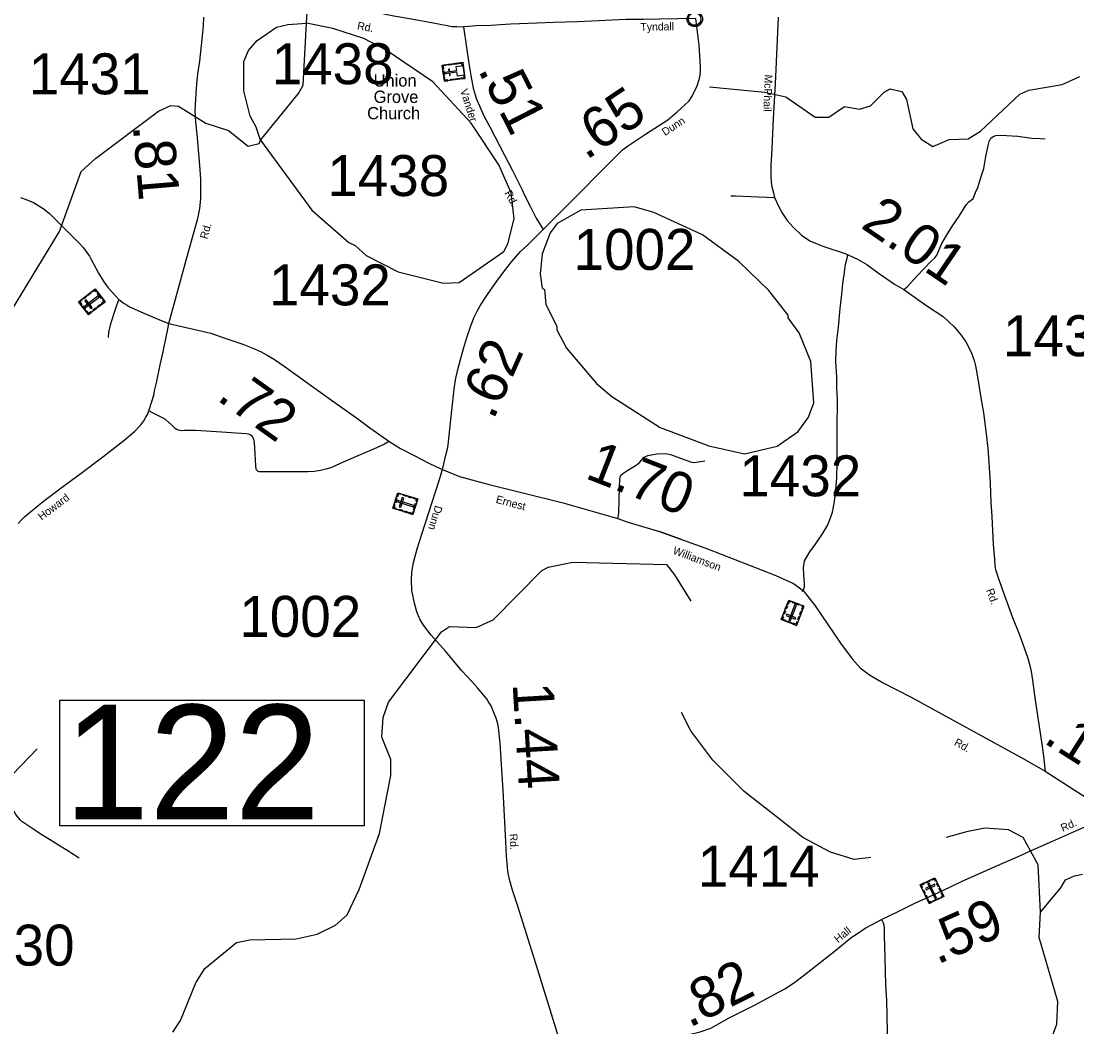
# Model space of a CAD drawing. Extents: x 2093524 to 2270757, y 289120 to 570408.
# Drawn here: x 2126907 to 2139794, y 473012 to 485292 of the extents above; entities that cross this region are included whole.
import ezdxf

# ---------------------------------------------------------------- set-up
doc = ezdxf.new("R2010")
doc.units = 0
for name, color, linetype in [('Exist Civil Demographics Community CELL', 7, 'Continuous'), ('Exist Cultural Cemetery CELL', 7, 'Continuous'), ('Exist Cultural Church with Cemetery CELL', 7, 'Continuous'), ('Exist Cultural Church with Cemetery Label', 7, 'Continuous'), ('Exist Hydrographic Creek Single Shore', 7, 'Continuous'), ('Exist Hydrographic Misc Water Feature', 7, 'Continuous'), ('Exist Hydrographic Pond Under 1500 Sq Ft', 7, 'Continuous'), ('Exist Road Non-System Type 51', 7, 'Continuous'), ('Exist Road Secondary Mileage Hundredths English Label', 7, 'Continuous'), ('Exist Road Secondary Structure Standard Bridge Number Label', 7, 'Continuous'), ('Exist Road Secondary Type 51 Attributed', 7, 'Continuous'), ('Exist Road Secondary Type 51 Label', 7, 'Continuous'), ('Exist Road Secondary Type 51 Number Label', 7, 'Continuous')]:
    doc.layers.add(name, color=color, linetype=linetype)

msp = doc.modelspace()

# ---------------------------------------------------------------- linework, layer by layer
at = {"layer": 'Exist Civil Demographics Community CELL'}
msp.add_lwpolyline([(2135205, 485294), (2135203, 485288), (2135200, 485283), (2135197, 485277), (2135194, 485272), (2135191, 485267), (2135186, 485262), (2135181, 485257), (2135176, 485253), (2135171, 485250), (2135167, 485247), (2135160, 485244), (2135153, 485241), (2135147, 485240), (2135140, 485239), (2135136, 485238), (2135131, 485238), (2135126, 485238), (2135121, 485238), (2135116, 485239), (2135110, 485240), (2135105, 485242), (2135100, 485243), (2135095, 485245), (2135092, 485248), (2135085, 485252), (2135079, 485256), (2135074, 485260), (2135070, 485265), (2135067, 485269), (2135064, 485273), (2135060, 485281), (2135058, 485284), (2135056, 485288), (2135054, 485296)], dxfattribs=at)
for centre, radius in [((2135130, 485317), 94.3), ((2135129, 485317), 76.7)]:
    msp.add_circle(centre, radius, dxfattribs=at)
at = {"layer": 'Exist Cultural Cemetery CELL'}
for points in [[(2127730, 481709), (2127608, 481866), (2127810, 482022), (2127932, 481864)], [(2127760, 481969), (2127725, 481942), (2127718, 481951), (2127753, 481978)], [(2127830, 481995), (2127821, 481988), (2127808, 482006), (2127776, 481981), (2127769, 481990), (2127810, 482022)], [(2127887, 481903), (2127836, 481970), (2127845, 481977), (2127896, 481909)], [(2127643, 481893), (2127650, 481884), (2127624, 481864), (2127649, 481832), (2127640, 481825), (2127608, 481866)], [(2127708, 481928), (2127673, 481902), (2127666, 481911), (2127701, 481937)], [(2127687, 481813), (2127698, 481798), (2127859, 481922), (2127847, 481937)], [(2127759, 481782), (2127774, 481794), (2127702, 481887), (2127687, 481876)], [(2127876, 481821), (2127842, 481795), (2127835, 481804), (2127869, 481830)], [(2127911, 481890), (2127902, 481883), (2127916, 481866), (2127884, 481841), (2127890, 481832), (2127932, 481864)], [(2127685, 481767), (2127653, 481808), (2127662, 481815), (2127694, 481774)], [(2127764, 481735), (2127757, 481744), (2127732, 481724), (2127707, 481756), (2127698, 481750), (2127730, 481709)], [(2127823, 481780), (2127789, 481754), (2127782, 481763), (2127816, 481789)], [(2131446, 479345), (2131506, 479534), (2131749, 479457), (2131688, 479267)], [(2131548, 479521), (2131544, 479510), (2131514, 479520), (2131501, 479482), (2131491, 479485), (2131506, 479534)], [(2131614, 479488), (2131573, 479501), (2131576, 479512), (2131617, 479499)], [(2131487, 479332), (2131490, 479342), (2131460, 479352), (2131472, 479391), (2131461, 479394), (2131446, 479345)], [(2131468, 479415), (2131484, 479465), (2131495, 479461), (2131479, 479412)], [(2131507, 479440), (2131501, 479422), (2131694, 479360), (2131700, 479378)], [(2131523, 479363), (2131541, 479357), (2131577, 479469), (2131559, 479475)], [(2131677, 479468), (2131635, 479481), (2131639, 479492), (2131680, 479479)], [(2131695, 479325), (2131721, 479406), (2131731, 479403), (2131706, 479322)], [(2131739, 479425), (2131728, 479429), (2131734, 479450), (2131696, 479462), (2131699, 479473), (2131749, 479457)], [(2131557, 479309), (2131516, 479322), (2131520, 479333), (2131561, 479320)], [(2131621, 479288), (2131580, 479302), (2131584, 479312), (2131625, 479299)], [(2131698, 479299), (2131687, 479302), (2131680, 479281), (2131642, 479293), (2131639, 479283), (2131688, 479267)], [(2136371, 477912), (2136185, 477984), (2136276, 478221), (2136462, 478150)], [(2136307, 478210), (2136303, 478199), (2136282, 478207), (2136268, 478169), (2136257, 478173), (2136276, 478221)], [(2136237, 478088), (2136222, 478048), (2136211, 478052), (2136227, 478092)], [(2136261, 478150), (2136245, 478110), (2136235, 478114), (2136250, 478154)], [(2136279, 477979), (2136297, 477972), (2136370, 478161), (2136352, 478168)], [(2136404, 478160), (2136325, 478190), (2136329, 478201), (2136408, 478171)], [(2136437, 478085), (2136421, 478044), (2136411, 478048), (2136426, 478089)], [(2136431, 478162), (2136427, 478151), (2136447, 478143), (2136433, 478106), (2136443, 478102), (2136462, 478150)], [(2136200, 478024), (2136211, 478020), (2136199, 477990), (2136237, 477976), (2136233, 477965), (2136185, 477984)], [(2136357, 477991), (2136364, 478008), (2136254, 478050), (2136247, 478033)], [(2136302, 477939), (2136253, 477958), (2136257, 477968), (2136306, 477950)], [(2136386, 477953), (2136376, 477957), (2136364, 477927), (2136326, 477941), (2136322, 477931), (2136371, 477912)], [(2136413, 478022), (2136397, 477982), (2136387, 477986), (2136402, 478026)], [(2137881, 474746), (2138061, 474832), (2138171, 474603), (2137991, 474517)], [(2137900, 474707), (2137910, 474712), (2137896, 474741), (2137933, 474759), (2137928, 474769), (2137881, 474746)], [(2137947, 474703), (2137955, 474686), (2138062, 474737), (2138054, 474753)], [(2137948, 474778), (2137995, 474801), (2138000, 474790), (2137953, 474768)], [(2137992, 474767), (2137975, 474759), (2138063, 474576), (2138080, 474584)], [(2138079, 474793), (2138069, 474788), (2138055, 474817), (2138019, 474800), (2138014, 474810), (2138061, 474832)], [(2138101, 474722), (2138082, 474762), (2138092, 474766), (2138111, 474727)], [(2137932, 474640), (2137913, 474679), (2137923, 474684), (2137942, 474645)], [(2137961, 474580), (2137942, 474619), (2137953, 474624), (2137971, 474585)], [(2138129, 474663), (2138111, 474702), (2138121, 474707), (2138140, 474668)], [(2138141, 474588), (2138136, 474599), (2138156, 474608), (2138138, 474645), (2138148, 474650), (2138171, 474603)], [(2138021, 474531), (2138016, 474541), (2137996, 474532), (2137979, 474568), (2137969, 474563), (2137991, 474517)], [(2138038, 474552), (2138115, 474589), (2138120, 474578), (2138043, 474542)]]:
    msp.add_lwpolyline(points, close=True, dxfattribs=at)
at = {"layer": 'Exist Cultural Church with Cemetery CELL'}
for points in [[(2132073, 484558), (2132046, 484755), (2132298, 484789), (2132325, 484592)], [(2132303, 484756), (2132291, 484755), (2132288, 484776), (2132248, 484771), (2132247, 484782), (2132298, 484789)], [(2132089, 484761), (2132090, 484749), (2132059, 484745), (2132064, 484705), (2132053, 484703), (2132046, 484755)], [(2132063, 484631), (2132056, 484682), (2132067, 484684), (2132074, 484632)], [(2132319, 484634), (2132304, 484745), (2132214, 484733), (2132221, 484683), (2132140, 484672), (2132136, 484705), (2132125, 484703), (2132129, 484671), (2132088, 484665), (2132089, 484654), (2132131, 484659), (2132135, 484626), (2132146, 484628), (2132142, 484661), (2132223, 484672), (2132229, 484622)], [(2132163, 484759), (2132120, 484753), (2132118, 484765), (2132161, 484770)], [(2132228, 484768), (2132185, 484762), (2132184, 484773), (2132227, 484779)], [(2132116, 484563), (2132114, 484575), (2132082, 484570), (2132077, 484610), (2132066, 484609), (2132073, 484558)], [(2132189, 484573), (2132146, 484567), (2132145, 484579), (2132187, 484585)], [(2132256, 484582), (2132213, 484576), (2132211, 484588), (2132254, 484594)], [(2132320, 484624), (2132309, 484623), (2132312, 484601), (2132272, 484596), (2132273, 484585), (2132325, 484592)]]:
    msp.add_lwpolyline(points, close=True, dxfattribs=at)
at = {"layer": 'Exist Hydrographic Creek Single Shore'}
for points in [[(2129829, 483840), (2130293, 484408), (2130351, 484508), (2130389, 485268)], [(2126384, 481094), (2127376, 482721), (2127639, 483457), (2127814, 483614), (2128586, 484193), (2128735, 484262), (2128827, 484253), (2129162, 484046), (2129437, 483956), (2129679, 483764), (2129812, 483797), (2129829, 483840)], [(2128760, 472947), (2128851, 473089), (2129041, 473548), (2129148, 473723), (2129538, 474043), (2129697, 474076), (2130263, 474088), (2130521, 474145), (2130745, 474255), (2130886, 474381), (2131035, 474689), (2131282, 475373), (2131421, 476082), (2131420, 476276), (2131310, 476550), (2131326, 476789), (2131392, 476975), (2132038, 477835), (2132137, 477902), (2132463, 477889), (2132670, 477980), (2133259, 478581), (2133342, 478625), (2133642, 478685), (2134783, 478656), (2134884, 478532), (2135083, 478211)], [(2137279, 475079), (2137077, 475057), (2136786, 475146), (2136449, 475326), (2136158, 475550), (2135732, 475887), (2135350, 476268), (2135081, 476627), (2134969, 476852)], [(2139228, 475161), (2139140, 475326), (2138961, 475416), (2138669, 475438), (2138445, 475393), (2138198, 475326)], [(2139348, 474412), (2139320, 474989), (2139228, 475161)], [(2139348, 474412), (2139599, 474711), (2139653, 474808), (2139763, 474855), (2139861, 474877)], [(2139119, 470161), (2139110, 470368), (2139241, 470818), (2139281, 471129), (2139285, 472152), (2139350, 472512), (2139548, 473046), (2139563, 473321), (2139335, 474103), (2139348, 474412)]]:
    msp.add_lwpolyline(points, dxfattribs=at)
at = {"layer": 'Exist Hydrographic Misc Water Feature'}
msp.add_line((2130389, 485268), (2130405, 485534), dxfattribs=at)
msp.add_lwpolyline([(2135308, 484491), (2135983, 484425), (2136241, 484367), (2136601, 484120), (2136767, 484120), (2136958, 484248), (2137141, 484215), (2137275, 484258), (2137441, 484425), (2137515, 484466), (2137657, 484434), (2137716, 484334), (2137792, 483975), (2137893, 483852), (2138035, 483760), (2138234, 483845), (2138468, 483853), (2138617, 483946), (2139098, 484399), (2139206, 484449), (2139614, 484516), (2139831, 484617)], dxfattribs=at)
at = {"layer": 'Exist Hydrographic Pond Under 1500 Sq Ft'}
for points in [[(2129829, 483840), (2129778, 483998), (2129703, 484131), (2129626, 484441), (2129625, 484798), (2129683, 484932), (2129790, 485057), (2130023, 485217), (2130164, 485250), (2130389, 485268)], [(2129829, 483840), (2130457, 482984), (2130909, 482588), (2130984, 482553), (2131118, 482429), (2131510, 482231), (2132061, 482092), (2132252, 482102), (2132801, 482478), (2132850, 482572), (2132924, 482879), (2132889, 483194), (2132738, 483535), (2132402, 484044), (2131933, 484549), (2131365, 484937), (2131090, 485081), (2130714, 485203), (2130389, 485268)], [(2135735, 480008), (2136135, 480101), (2136392, 480280), (2136516, 480455), (2136582, 480630), (2136547, 481136), (2136404, 481487), (2136270, 481670), (2136269, 481703), (2136035, 482003), (2135667, 482358), (2135224, 482682), (2134631, 482953), (2134389, 483026), (2133740, 482984), (2133449, 482822), (2133366, 482706), (2133267, 482449), (2133243, 482206), (2133269, 482032), (2133294, 482015), (2133312, 481831), (2133446, 481566), (2133446, 481523), (2133564, 481298), (2133932, 480867), (2134116, 480709), (2134709, 480330), (2135302, 480108), (2135735, 480008)]]:
    msp.add_lwpolyline(points, dxfattribs=at)
at = {"layer": 'Exist Road Non-System Type 51'}
for points in [[(2137683, 482014), (2137722, 482049), (2137846, 482183), (2138016, 482359), (2138061, 482400), (2138083, 482436), (2138146, 482575), (2138202, 482674), (2138276, 482792), (2138357, 482910), (2138408, 482997), (2138441, 483047), (2138474, 483084), (2138505, 483107), (2138527, 483127), (2138537, 483145), (2138558, 483198), (2138584, 483262), (2138631, 483407), (2138658, 483492), (2138683, 483638), (2138710, 483773), (2138725, 483823), (2138744, 483861), (2138770, 483884), (2138806, 483895), (2138864, 483898), (2139074, 483886), (2139244, 483863), (2139346, 483857), (2139406, 483853)], [(2135570, 483160), (2135628, 483159), (2135906, 483146), (2136101, 483138)], [(2136439, 478329), (2136456, 478349), (2136468, 478383), (2136469, 478419), (2136459, 478537), (2136455, 478615), (2136464, 478675), (2136471, 478701), (2136533, 478812), (2136605, 478906), (2136687, 479032), (2136751, 479133), (2136776, 479193), (2136812, 479296), (2136837, 479427), (2136852, 479561), (2136863, 479719), (2136867, 479899), (2136867, 480113), (2136869, 480407), (2136872, 480571), (2136872, 480668), (2136865, 480819), (2136862, 480947), (2136854, 481069), (2136853, 481141), (2136856, 481263), (2136864, 481391), (2136882, 481556), (2136904, 481784), (2136924, 481957), (2136938, 482089), (2136952, 482193), (2136971, 482326), (2136991, 482398), (2136997, 482440)], [(2128102, 481892), (2128087, 481863), (2128068, 481807), (2128035, 481709), (2127994, 481578), (2127975, 481492), (2127968, 481430)], [(2131393, 480154), (2131344, 480125), (2131208, 480066), (2131075, 480007), (2130930, 479948), (2130801, 479890), (2130688, 479838), (2130626, 479820), (2130561, 479803), (2130485, 479793), (2130409, 479788), (2130133, 479790), (2129899, 479790), (2129851, 479789), (2129827, 479788), (2129813, 479790), (2129801, 479794), (2129793, 479800), (2129782, 479815), (2129778, 479825), (2129772, 479861), (2129759, 480083), (2129756, 480141), (2129747, 480187), (2129741, 480201), (2129730, 480220), (2129720, 480230), (2129702, 480240), (2129684, 480248), (2129654, 480253), (2129592, 480256), (2129291, 480278), (2129037, 480293), (2128903, 480292), (2128861, 480291), (2128829, 480296), (2128805, 480304), (2128786, 480316), (2128745, 480357), (2128668, 480427), (2128634, 480450), (2128520, 480506), (2128465, 480534)], [(2134189, 479218), (2134201, 479286), (2134206, 479444), (2134211, 479608), (2134215, 479690), (2134221, 479722), (2134228, 479746), (2134250, 479769), (2134311, 479810), (2134416, 479870), (2134455, 479903), (2134512, 479966), (2134557, 479987), (2134665, 480009), (2134767, 480013), (2134835, 479999), (2135079, 479912), (2135117, 479904), (2135177, 479909), (2135253, 479921)], [(2127614, 475071), (2127560, 475108), (2127458, 475174), (2127362, 475231), (2127252, 475301), (2127141, 475369), (2127062, 475422), (2126941, 475502), (2126915, 475521), (2126897, 475539), (2126844, 475604), (2126755, 475767), (2126631, 475999), (2126447, 476366), (2126279, 476697), (2126082, 477028)]]:
    msp.add_lwpolyline(points, dxfattribs=at)
at = {"layer": 'Exist Road Secondary Structure Standard Bridge Number Label'}
msp.add_lwpolyline([(2127381, 477001), (2131096, 477001), (2131096, 475465), (2127381, 475465)], close=True, dxfattribs=at)
msp.add_lwpolyline([(2125264, 472682), (2125797, 475053), (2127103, 476408)], dxfattribs=at)
at = {"layer": 'Exist Road Secondary Type 51 Attributed'}
for points in [[(2129129, 485797), (2129308, 485764), (2129506, 485726), (2129598, 485709), (2129825, 485665), (2130004, 485634), (2130212, 485589), (2130381, 485564), (2130461, 485549), (2130754, 485492), (2130995, 485448), (2131215, 485404), (2131456, 485358), (2131673, 485321), (2131937, 485272), (2132106, 485238), (2132168, 485227), (2132226, 485224), (2132308, 485223)], [(2128711, 481598), (2128945, 482462), (2129064, 482880), (2129088, 483002), (2129100, 483120), (2129102, 483226), (2129102, 483364), (2129084, 483582), (2129056, 483910), (2129040, 484062), (2129035, 484129), (2129032, 484203), (2129037, 484260), (2129044, 484412), (2129054, 484522), (2129066, 484648), (2129088, 484804), (2129119, 485071), (2129132, 485233), (2129137, 485339)], [(2135141, 485324), (2134703, 485317), (2134505, 485313), (2134293, 485310), (2133699, 485283), (2133405, 485275), (2133208, 485265), (2132882, 485254), (2132580, 485234), (2132504, 485239), (2132370, 485227), (2132308, 485223)], [(2133279, 482746), (2133413, 482881), (2133739, 483207), (2133958, 483430), (2134099, 483571), (2134188, 483658), (2134246, 483720), (2134321, 483773), (2134527, 483913), (2134799, 484087), (2134915, 484183), (2135002, 484263), (2135062, 484318), (2135097, 484375), (2135157, 484500), (2135187, 484591), (2135196, 484633), (2135201, 484693), (2135200, 484743), (2135183, 484999), (2135141, 485324)], [(2136148, 485340), (2136109, 484523), (2136085, 484104), (2136069, 483732), (2136059, 483530), (2136057, 483402), (2136063, 483320), (2136074, 483252), (2136089, 483194), (2136101, 483138), (2136155, 483025), (2136200, 482942), (2136258, 482859), (2136332, 482775), (2136432, 482679), (2136533, 482611), (2136692, 482544), (2136964, 482456), (2137114, 482387), (2137229, 482321), (2137367, 482218), (2137566, 482082), (2137683, 482014), (2137963, 481815), (2138160, 481685), (2138294, 481558), (2138380, 481458), (2138438, 481377), (2138505, 481250), (2138539, 481147), (2138556, 481081), (2138585, 480926), (2138622, 480691), (2138653, 480511), (2138687, 480252), (2138706, 480072), (2138719, 479912), (2138737, 479645), (2138745, 479419), (2138755, 479243), (2138770, 478901), (2138787, 478722), (2138793, 478640), (2138802, 478598), (2138827, 478512), (2138876, 478367), (2139008, 478010), (2139092, 477798), (2139191, 477526), (2139221, 477424), (2139235, 477350), (2139253, 477247), (2139272, 477091), (2139297, 476918), (2139363, 476493), (2139386, 476318), (2139406, 476133)], [(2132308, 485223), (2132344, 484968), (2132370, 484773), (2132396, 484626), (2132426, 484473), (2132450, 484391), (2132465, 484339), (2132502, 484257), (2132554, 484137), (2132629, 484001), (2132750, 483766), (2132904, 483467), (2133024, 483232), (2133050, 483168), (2133119, 483031), (2133195, 482886), (2133279, 482746)], [(2126898, 483138), (2126970, 483115), (2127057, 483077), (2127178, 483003), (2127255, 482942), (2127336, 482861), (2127617, 482582), (2127670, 482525), (2127711, 482465), (2127740, 482420), (2127758, 482390), (2127783, 482345), (2127853, 482216), (2127919, 482107), (2127968, 482037), (2128017, 481984), (2128062, 481933), (2128102, 481892), (2128165, 481843), (2128200, 481823), (2128232, 481804), (2128286, 481777), (2128407, 481725), (2128615, 481636), (2128711, 481598)], [(2132052, 479819), (2132097, 480007), (2132114, 480084), (2132125, 480156), (2132142, 480308), (2132164, 480537), (2132194, 480797), (2132210, 480913), (2132238, 481038), (2132270, 481160), (2132312, 481305), (2132347, 481430), (2132393, 481560), (2132435, 481669), (2132472, 481752), (2132513, 481822), (2132606, 481968), (2132712, 482116), (2132806, 482241), (2132898, 482355), (2133004, 482477), (2133089, 482558), (2133172, 482641), (2133279, 482746)], [(2126870, 479159), (2126921, 479212), (2126949, 479239), (2127020, 479302), (2127160, 479414), (2127379, 479580), (2127640, 479772), (2127906, 479973), (2128163, 480171), (2128295, 480287), (2128370, 480364), (2128405, 480411), (2128430, 480455), (2128452, 480496), (2128465, 480534), (2128504, 480648), (2128526, 480725), (2128537, 480779), (2128559, 480875), (2128606, 481094), (2128639, 481237), (2128693, 481510), (2128711, 481598)], [(2128711, 481598), (2129223, 481482), (2129394, 481422), (2129613, 481348), (2129734, 481300), (2129828, 481258), (2129909, 481215), (2130002, 481159), (2130117, 481078), (2130247, 480985), (2130480, 480818), (2130751, 480621), (2131002, 480449), (2131164, 480326), (2131326, 480212), (2131407, 480153), (2131536, 480072), (2131714, 479983), (2131861, 479908), (2131985, 479847), (2132052, 479819)], [(2133521, 472721), (2133211, 473721), (2132967, 474499), (2132906, 474681), (2132869, 474811), (2132849, 474908), (2132844, 474966), (2132833, 475096), (2132824, 475274), (2132791, 475903), (2132768, 476277), (2132756, 476479), (2132734, 476668), (2132721, 476728), (2132705, 476782), (2132672, 476859), (2132644, 476932), (2132613, 476982), (2132591, 477019), (2132564, 477051), (2132476, 477151), (2132407, 477228), (2132286, 477361), (2132091, 477595), (2131911, 477794), (2131817, 477918), (2131773, 477991), (2131737, 478078), (2131707, 478186), (2131678, 478341), (2131672, 478467), (2131676, 478565), (2131697, 478682), (2131742, 478847), (2131798, 479026), (2131883, 479293), (2132011, 479682), (2132052, 479819)], [(2132052, 479819), (2132260, 479731), (2132621, 479636), (2133507, 479414), (2134189, 479218), (2134300, 479180), (2134700, 479062), (2134954, 478965), (2134700, 479062), (2135286, 478848), (2136118, 478524), (2136334, 478426), (2136451, 478338), (2136598, 478152), (2136910, 477696), (2137051, 477507), (2137148, 477397), (2137261, 477309), (2137423, 477218), (2137769, 477037), (2139157, 476275), (2139406, 476133)], [(2139406, 476133), (2139862, 475842), (2140129, 475676), (2140196, 475631), (2140321, 475573)], [(2139228, 475161), (2139459, 475263), (2139752, 475395), (2139919, 475468), (2140057, 475521), (2140126, 475540), (2140196, 475556), (2140321, 475573)], [(2137409, 474321), (2137603, 474417), (2137817, 474522), (2137954, 474582), (2138158, 474679), (2138384, 474785), (2138796, 474971), (2139068, 475089), (2139228, 475161)], [(2133521, 472721), (2133598, 472747), (2133832, 472790), (2134067, 472814), (2134245, 472830), (2134534, 472854), (2134894, 472889), (2135063, 472918), (2135194, 472951), (2135326, 472998), (2135551, 473122), (2135866, 473280), (2136064, 473386), (2136161, 473438), (2136228, 473478), (2136335, 473546), (2136398, 473595), (2136488, 473665), (2136851, 473950), (2137040, 474102), (2137115, 474154), (2137209, 474219), (2137302, 474267), (2137409, 474321)], [(2137409, 474321), (2137428, 474284), (2137437, 474252), (2137441, 474226), (2137440, 474204), (2137442, 474178), (2137443, 474126), (2137451, 473856), (2137457, 473524), (2137469, 473333), (2137486, 472585)]]:
    msp.add_lwpolyline(points, dxfattribs=at)

# ---------------------------------------------------------------- texts
at = {"layer": 'Exist Cultural Church with Cemetery Label'}
for s, p in [('Union', (2131210, 484492)), ('Grove', (2131210, 484293)), ('Church', (2131131, 484093))]:
    msp.add_text(s, height=150, dxfattribs=at).set_placement(p)
at = {"layer": 'Exist Road Secondary Mileage Hundredths English Label'}
for s, rotation, p in [('.51', 297.0771, (2132477, 484697)), ('.65', 34.0591, (2133803, 483588)), ('.81', 274.8346, (2128270, 484014)), ('2.01', 325.6607, (2137142, 482777)), ('.62', 66.0438, (2132672, 480411)), ('.72', 324.4714, (2129282, 480674)), ('1.70', 338.682, (2133778, 479716)), ('1.44', 273.4391, (2132906, 477203)), ('.19', 327.6104, (2139371, 476490)), ('.59', 24.2782, (2138090, 473768)), ('.82', 26.5796, (2135061, 472995))]:
    msp.add_text(s, height=500, rotation=rotation, dxfattribs=at).set_placement(p)
at = {"layer": 'Exist Road Secondary Structure Standard Bridge Number Label'}
msp.add_text('122', height=1400, dxfattribs=at).set_placement((2127431, 475544))
at = {"layer": 'Exist Road Secondary Type 51 Label'}
for s, rotation, p in [('Rd.', 349.6408, (2131004, 485192)), ('Tyndall', 1.1566, (2134468, 485173)), ('McPhail', 267.8586, (2135984, 484640)), ('Vander', 287.9623, (2132264, 484445)), ('Dunn', 32.7448, (2134766, 483887)), ('Rd.', 298.3507, (2132804, 483193)), ('Rd.', 74.0909, (2129179, 482624)), ('Howard', 37.0579, (2127158, 479191)), ('Ernest', 345.0185, (2132695, 479412)), ('Dunn', 252.8344, (2131963, 479385)), ('Williamson', 339.3302, (2134854, 478791)), ('Rd.', 290.4255, (2138684, 478344)), ('Rd.', 330.7441, (2138287, 476458)), ('Rd.', 24.2903, (2139622, 475391)), ('Rd.', 272.7311, (2132869, 475369)), ('Hall', 38.8445, (2136877, 474033))]:
    msp.add_text(s, height=95, rotation=rotation, dxfattribs=at).set_placement(p)
at = {"layer": 'Exist Road Secondary Type 51 Number Label'}
for s, p in [('1438', (2129966, 484521)), ('1431', (2127001, 484398)), ('1438', (2130645, 483156)), ('1002', (2133651, 482254)), ('1432', (2129933, 481821)), ('1433', (2138891, 481200)), ('1432', (2135674, 479490)), ('1002', (2129571, 477774)), ('1414', (2135167, 474724)), ('1430', (2126072, 473760))]:
    msp.add_text(s, height=500, dxfattribs=at).set_placement(p)

doc.saveas('drawing.dxf')
